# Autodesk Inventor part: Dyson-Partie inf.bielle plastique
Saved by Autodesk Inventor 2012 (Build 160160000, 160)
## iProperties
Created: 2012-11
Part Number: Dyson-Partie inf.bielle plastique
Material: Default
Document SubType Name: Modeling
Designer: Administrateur
Density: 1 g/cm^3
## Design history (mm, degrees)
node "Dyson-Partie inf.bielle plastique1"
node "Dyson-Partie inf.bielle plastique"
node "Base1"
